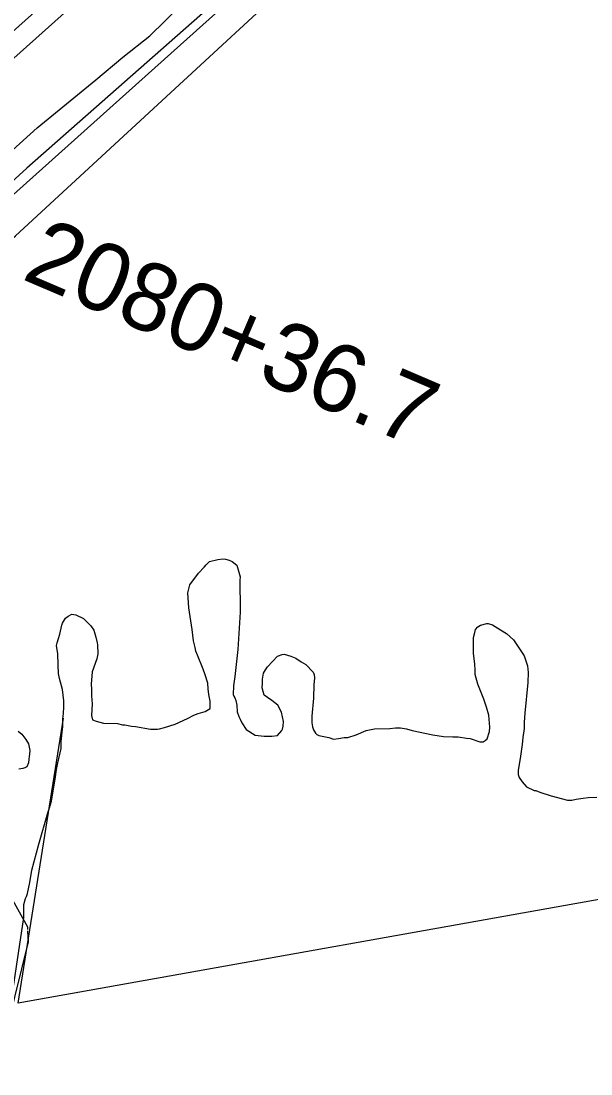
# Model space of a CAD drawing. Extents: x 3245246 to 3283090, y 806824 to 832173.
# Drawn here: x 3257217 to 3258055, y 814501 to 816050 of the extents above; entities that cross this region are included whole.
import ezdxf

# ---------------------------------------------------------------- set-up
doc = ezdxf.new("R2010")
doc.units = 0
for name, color, linetype in [('V-LEVE-TOET', 7, 'Continuous'), ('V-ROAD-CNTR', 7, 'Continuous'), ('V-SITE-VEGE', 7, 'Continuous'), ('V-SURV-IDEN', 7, 'Continuous'), ('V-SURV-LINE', 7, 'Continuous'), ('V-TOPO-SHOR', 7, 'Continuous')]:
    doc.layers.add(name, color=color, linetype=linetype)

msp = doc.modelspace()

# ---------------------------------------------------------------- linework, layer by layer
at = {"layer": 'V-LEVE-TOET'}
msp.add_lwpolyline([(3257204.2, 815859.5), (3257240.5, 815892.4), (3257326.6, 815963.1), (3257366.4, 815996.7), (3257406.3, 816027.9), (3257450.6, 816071.4)], dxfattribs=at)
at = {"layer": 'V-ROAD-CNTR'}
for points in [[(3259145.2, 817529.9), (3258836.8, 817255.7), (3258084.2, 816582.5), (3257451.2, 816014.9), (3257158.3, 815752.6)], [(3257226.6, 814713.1), (3257226.5, 814716.6), (3257214.5, 814738.9), (3257207.3, 814751.9), (3257200.1, 814763.2), (3257185.9, 814775.7), (3257166.2, 814782.6), (3257136.8, 814786.8), (3257132.7, 814786.9)], [(3257040.9, 813232.7), (3257080.5, 813594), (3257126.2, 813997), (3257172.5, 814370), (3257197.9, 814573.8), (3257217.8, 814655.5), (3257227.5, 814694.9), (3257226.7, 814711.2)]]:
    msp.add_lwpolyline(points, dxfattribs=at)
at = {"layer": 'V-SITE-VEGE'}
for p, q in [((3257489, 815249.8), (3257494, 815254.8)), ((3257494, 815254.8), (3257505.9, 815257.5)), ((3257505.9, 815257.5), (3257513.6, 815258.5)), ((3257513.6, 815258.5), (3257517.2, 815258.1)), ((3257517.2, 815258.1), (3257522.9, 815256.8)), ((3257522.9, 815256.8), (3257527.2, 815254.5)), ((3257527.2, 815254.5), (3257534.2, 815249.1)), ((3257465, 815220.3), (3257477.7, 815237.5)), ((3257477.7, 815237.5), (3257486, 815246.2)), ((3257486, 815246.2), (3257489, 815249.8)), ((3257534.2, 815249.1), (3257538.8, 815231.9)), ((3257463.4, 815214.6), (3257465, 815220.3)), ((3257538.5, 815227.2), (3257538.2, 815211.3)), ((3257538.8, 815231.9), (3257538.5, 815227.2)), ((3257462.1, 815208.6), (3257463.4, 815214.6)), ((3257463.4, 815186.7), (3257462.1, 815208.6)), ((3257538.2, 815211.3), (3257539.1, 815199)), ((3257539.1, 815199), (3257538.8, 815180)), ((3257282.2, 815171.1), (3257285.9, 815174.4)), ((3257285.9, 815174.4), (3257291.6, 815177.4)), ((3257291.6, 815177.4), (3257297.2, 815176.4)), ((3257297.2, 815176.4), (3257308.5, 815170.8)), ((3257468.3, 815154.8), (3257463.4, 815186.7)), ((3257538.8, 815180), (3257535.5, 815125.2)), ((3257273.6, 815147.9), (3257276.9, 815160.8)), ((3257276.9, 815160.8), (3257277.9, 815164.1)), ((3257277.9, 815164.1), (3257282.2, 815171.1)), ((3257308.5, 815170.8), (3257319.5, 815159.8)), ((3257319.5, 815159.8), (3257323.5, 815153.8)), ((3257885.1, 815154.7), (3257888.1, 815158.7)), ((3257888.1, 815158.7), (3257892.4, 815161)), ((3257892.4, 815161), (3257901.4, 815163.3)), ((3257901.4, 815163.3), (3257903.7, 815163.3)), ((3257903.7, 815163.3), (3257909.7, 815161.6)), ((3257909.7, 815161.6), (3257921.6, 815154.3)), ((3257269.9, 815135.2), (3257273.6, 815147.9)), ((3257323.5, 815153.8), (3257326.8, 815143.5)), ((3257326.8, 815143.5), (3257328.8, 815134.9)), ((3257470.3, 815137.8), (3257468.3, 815154.8)), ((3257882.1, 815142.7), (3257883.8, 815150.3)), ((3257882.1, 815119.8), (3257882.1, 815142.7)), ((3257883.8, 815150.3), (3257885.1, 815154.7)), ((3257921.6, 815154.3), (3257930.3, 815148.7)), ((3257930.3, 815148.7), (3257940.6, 815139.4)), ((3257268.9, 815131.2), (3257269.9, 815135.2)), ((3257269.9, 815124.9), (3257268.9, 815131.2)), ((3257328.8, 815134.9), (3257329.1, 815131.9)), ((3257329.1, 815131.9), (3257329.8, 815118.6)), ((3257472.7, 815128.2), (3257470.3, 815137.8)), ((3257473.7, 815122.6), (3257472.7, 815128.2)), ((3257940.6, 815139.4), (3257956.5, 815115.8)), ((3257270.6, 815119.3), (3257269.9, 815124.9)), ((3257271.3, 815102), (3257270.6, 815119.3)), ((3257328.1, 815111.3), (3257321.1, 815092.3)), ((3257329.8, 815118.6), (3257328.1, 815111.3)), ((3257476.3, 815116.9), (3257473.7, 815122.6)), ((3257484.6, 815096.3), (3257476.3, 815116.9)), ((3257535.5, 815125.2), (3257531.1, 815085.6)), ((3257579, 815099.9), (3257594, 815115.2)), ((3257594, 815115.2), (3257600.6, 815117.9)), ((3257600.6, 815117.9), (3257603.6, 815118.2)), ((3257603.6, 815118.2), (3257613.6, 815115.2)), ((3257613.6, 815115.2), (3257620.5, 815112.5)), ((3257620.5, 815112.5), (3257628.8, 815107.2)), ((3257884.1, 815103.8), (3257882.1, 815119.8)), ((3257956.5, 815115.8), (3257961.2, 815101.1)), ((3257271.9, 815090), (3257271.3, 815102)), ((3257487.6, 815088), (3257484.6, 815096.3)), ((3257576, 815095.3), (3257579, 815099.9)), ((3257628.8, 815107.2), (3257635.2, 815102.9)), ((3257635.2, 815102.9), (3257646.1, 815091.9)), ((3257884.4, 815094.8), (3257884.1, 815103.8)), ((3257961.2, 815101.1), (3257962.2, 815091.2)), ((3257273.2, 815082.4), (3257271.9, 815090)), ((3257277.6, 815066.1), (3257273.2, 815082.4)), ((3257321.1, 815092.3), (3257319.8, 815074.4)), ((3257491.3, 815075.7), (3257487.6, 815088)), ((3257531.1, 815085.6), (3257529.1, 815071.7)), ((3257571.7, 815081.6), (3257573.3, 815090.3)), ((3257571.7, 815075), (3257571.7, 815081.6)), ((3257573.3, 815090.3), (3257576, 815095.3)), ((3257646.1, 815091.9), (3257647.8, 815088.3)), ((3257648.4, 815083), (3257647.4, 815073.6)), ((3257647.8, 815088.3), (3257648.4, 815083)), ((3257884.4, 815088.5), (3257884.4, 815094.8)), ((3257888.1, 815074.2), (3257884.4, 815088.5)), ((3257962.2, 815091.2), (3257961.8, 815076.5)), ((3257279.6, 815049.8), (3257277.6, 815066.1)), ((3257319.8, 815074.4), (3257320.1, 815066.8)), ((3257320.1, 815066.8), (3257320.1, 815057.1)), ((3257491.9, 815067.4), (3257491.3, 815075.7)), ((3257492.9, 815059.1), (3257491.9, 815067.4)), ((3257529.1, 815071.7), (3257528.8, 815059.1)), ((3257571.3, 815069), (3257571.7, 815075)), ((3257574, 815058), (3257571.3, 815069)), ((3257647.4, 815073.6), (3257646.8, 815053.7)), ((3257897, 815052), (3257888.1, 815074.2)), ((3257961.8, 815076.5), (3257957.5, 815031.7)), ((3257279.6, 815040.8), (3257279.6, 815049.8)), ((3257320.1, 815057.1), (3257321.1, 815045.5)), ((3257494.6, 815049.4), (3257492.9, 815059.1)), ((3257494.6, 815038.5), (3257494.6, 815049.4)), ((3257528.8, 815059.1), (3257529.5, 815056.7)), ((3257529.5, 815056.7), (3257531.1, 815054.1)), ((3257531.1, 815054.1), (3257532.5, 815050.4)), ((3257532.5, 815050.4), (3257533.8, 815043.1)), ((3257579, 815054.7), (3257574, 815058)), ((3257585.3, 815050.1), (3257579, 815054.7)), ((3257594.3, 815043.1), (3257585.3, 815050.1)), ((3257646.8, 815053.7), (3257644.1, 815027.1)), ((3257901, 815040.3), (3257897, 815052)), ((3257279.2, 815031.2), (3257279.6, 815040.8)), ((3257321.1, 815045.5), (3257320.1, 815027.9)), ((3257477.3, 815031.2), (3257487.6, 815034.1)), ((3257487.6, 815034.1), (3257494.6, 815038.5)), ((3257533.8, 815043.1), (3257534.4, 815033.5)), ((3257599.9, 815032.8), (3257594.3, 815043.1)), ((3257904.3, 815028.4), (3257901, 815040.3)), ((3257278.2, 815023.2), (3257279.2, 815031.2)), ((3257278.2, 815011.6), (3257278.2, 815023.2)), ((3257320.1, 815027.9), (3257321.8, 815021.9)), ((3257321.8, 815021.9), (3257327.4, 815019.6)), ((3257327.4, 815019.6), (3257338, 815016.6)), ((3257443.4, 815015.2), (3257461.3, 815023.8)), ((3257461.3, 815023.8), (3257470.6, 815028.8)), ((3257470.6, 815028.8), (3257477.3, 815031.2)), ((3257534.4, 815033.5), (3257536.8, 815026.5)), ((3257536.8, 815026.5), (3257539.1, 815022.5)), ((3257539.1, 815022.5), (3257541.4, 815017.5)), ((3257602.6, 815019.2), (3257599.9, 815032.8)), ((3257601.9, 815012.2), (3257602.6, 815019.2)), ((3257644.1, 815027.1), (3257644.1, 815017.2)), ((3257906, 815010.8), (3257904.3, 815028.4)), ((3257957.5, 815031.7), (3257956.5, 815018.1)), ((3257275.9, 814989.7), (3257277.5, 815008)), ((3257277.5, 815008), (3257278.2, 815011.6)), ((3257338, 815016.6), (3257358.3, 815016.2)), ((3257358.3, 815016.2), (3257365.9, 815014.6)), ((3257365.9, 815014.6), (3257369.3, 815014.6)), ((3257369.3, 815014.6), (3257379.2, 815012.6)), ((3257379.2, 815012.6), (3257385.2, 815011.9)), ((3257385.2, 815011.9), (3257407.2, 815008.2)), ((3257407.2, 815008.2), (3257417.1, 815008.2)), ((3257417.1, 815008.2), (3257420.5, 815008.6)), ((3257420.5, 815008.6), (3257427.8, 815010.2)), ((3257427.8, 815010.2), (3257443.4, 815015.2)), ((3257541.4, 815017.5), (3257547.7, 815007.5)), ((3257547.7, 815007.5), (3257561, 814999.2)), ((3257593.6, 814998.9), (3257600.2, 815005.9)), ((3257600.2, 815005.9), (3257600.9, 815007.9)), ((3257600.9, 815007.9), (3257601.9, 815012.2)), ((3257644.1, 815017.2), (3257645.1, 815011.2)), ((3257645.1, 815011.2), (3257646.8, 815006.8)), ((3257646.8, 815006.8), (3257649.8, 815001.9)), ((3257709.2, 814999.5), (3257723.9, 815006.2)), ((3257723.9, 815006.2), (3257736.2, 815008.5)), ((3257736.2, 815008.5), (3257759.1, 815009.1)), ((3257759.1, 815009.1), (3257767.1, 815009.8)), ((3257767.1, 815009.8), (3257774.4, 815009.8)), ((3257774.4, 815009.8), (3257783.4, 815008.5)), ((3257783.4, 815008.5), (3257792, 815006.1)), ((3257792, 815006.1), (3257822.2, 814999.5)), ((3257902, 814993.8), (3257905.3, 815004.8)), ((3257905.3, 815004.8), (3257906, 815010.8)), ((3257956.2, 815008.8), (3257954.5, 814995.5)), ((3257956.5, 815018.1), (3257956.2, 815008.8)), ((3257275.5, 814979.4), (3257275.9, 814989.7)), ((3257561, 814999.2), (3257574.3, 814997.6)), ((3257574.3, 814997.6), (3257585.6, 814997.6)), ((3257585.6, 814997.6), (3257593.6, 814998.9)), ((3257649.8, 815001.9), (3257651.8, 814999.9)), ((3257651.8, 814999.9), (3257654.7, 814998.5)), ((3257654.7, 814998.5), (3257669.4, 814995.5)), ((3257669.4, 814995.5), (3257676.3, 814993.5)), ((3257676.3, 814993.5), (3257683.3, 814994.2)), ((3257683.3, 814994.2), (3257691.6, 814995.5)), ((3257691.6, 814995.5), (3257697.3, 814995.9)), ((3257697.3, 814995.9), (3257709.2, 814999.5)), ((3257822.2, 814999.5), (3257837.9, 814997.2)), ((3257837.9, 814997.2), (3257851.5, 814996.5)), ((3257851.5, 814996.5), (3257859.5, 814996.8)), ((3257859.5, 814996.8), (3257871.7, 814994.8)), ((3257871.7, 814994.8), (3257877.1, 814994.2)), ((3257877.1, 814994.2), (3257891.4, 814989.5)), ((3257891.4, 814989.5), (3257894, 814989.2)), ((3257894, 814989.2), (3257896.3, 814989.2)), ((3257896.3, 814989.2), (3257899.3, 814991.5)), ((3257899.3, 814991.5), (3257902, 814993.8)), ((3257954.5, 814995.5), (3257953.5, 814985.2)), ((3257270.9, 814958.4), (3257275.5, 814979.4)), ((3257953.5, 814985.2), (3257950.8, 814964.9)), ((3257268.6, 814948.8), (3257270.9, 814958.4)), ((3257950.8, 814964.9), (3257947.5, 814947.9)), ((3257267.2, 814937.8), (3257268.6, 814948.8)), ((3257947.5, 814947.9), (3257947.5, 814941.3)), ((3257947.5, 814941.3), (3257949.2, 814937)), ((3257261.6, 814902.3), (3257267.2, 814937.8)), ((3257949.2, 814937), (3257953.5, 814930.3)), ((3257953.5, 814930.3), (3257959.8, 814923.3)), ((3257959.8, 814923.3), (3257971.1, 814918)), ((3257971.1, 814918), (3257973.4, 814917.7)), ((3257973.4, 814917.7), (3257979.4, 814915.4)), ((3257979.4, 814915.4), (3257996, 814909.7)), ((3257258.2, 814891), (3257261.6, 814902.3)), ((3257996, 814909.7), (3258020.3, 814903.7)), ((3258020.3, 814903.7), (3258026.6, 814903.4)), ((3258026.6, 814903.4), (3258032.9, 814905)), ((3258032.9, 814905), (3258043.2, 814906.7)), ((3258043.2, 814906.7), (3258050.5, 814907.7)), ((3258050.5, 814907.7), (3258063.5, 814908)), ((3257242.9, 814838.8), (3257255.9, 814884.7)), ((3257255.9, 814884.7), (3257258.2, 814891)), ((3257232.6, 814800.6), (3257242.9, 814838.8)), ((3257229.6, 814782.3), (3257232.6, 814800.6)), ((3257226, 814766), (3257229.6, 814782.3)), ((3257220.6, 814750.1), (3257223.3, 814759.1)), ((3257223.3, 814759.1), (3257224.6, 814762)), ((3257224.6, 814762), (3257226, 814766)), ((3257220.6, 814730.8), (3257220.6, 814750.1)), ((3257187, 814504.8), (3257220.6, 814730.8))]:
    msp.add_line(p, q, dxfattribs=at)
msp.add_lwpolyline([(3257212.4, 815004.9), (3257217.7, 815000.6), (3257220.7, 814996.9), (3257223.7, 814992.6), (3257227.6, 814986.3), (3257229.6, 814976.7), (3257229.3, 814971), (3257228.6, 814968), (3257228.3, 814963.7), (3257227.6, 814958.7), (3257225.3, 814952.7), (3257222.3, 814951.1), (3257219.3, 814950.1), (3257213.3, 814949.1)], dxfattribs=at)
at = {"layer": 'V-SURV-LINE'}
for points in [[(3257046.5, 815892.9), (3259111.3, 817740.4)], [(3259131.3, 817718.1), (3257066.5, 815870.5)]]:
    msp.add_lwpolyline(points, dxfattribs=at)
at = {"layer": 'V-TOPO-SHOR'}
for points in [[(3260152.6, 818148.3), (3259812.1, 817949.2), (3259413.6, 817737.7), (3259264.1, 817646.5), (3259201.8, 817596.7), (3259035.7, 817443.2), (3258545.8, 817011.7), (3258321.5, 816825.1), (3257956.1, 816493.2), (3257545.1, 816115.6), (3257225.3, 815833.5), (3257084.2, 815704.9), (3257013.6, 815651), (3256897.3, 815568), (3256357.6, 815240.4)], [(3257985.2, 816455.8), (3258271.7, 816721.3), (3258404.6, 816833.3), (3258346.3, 816480.5), (3258275.6, 816069.7), (3258225.5, 815555), (3258179.7, 815110.9), (3258162.9, 814774.7), (3257212.3, 814604.9), (3257278.9, 815024.1)], [(3256062.8, 814995.6), (3256345.1, 815169.8), (3256810.1, 815456), (3257009.4, 815588.7), (3257109, 815646.8), (3257208.7, 815733.9), (3257702.8, 816190.3), (3257918.7, 816401.9)]]:
    msp.add_lwpolyline(points, dxfattribs=at)

# ---------------------------------------------------------------- texts
at = {"layer": 'V-SURV-IDEN'}
msp.add_text('2080+36.7', height=100, rotation=336.7973, dxfattribs=at).set_placement((3257215.8, 815671))

doc.saveas('drawing.dxf')
